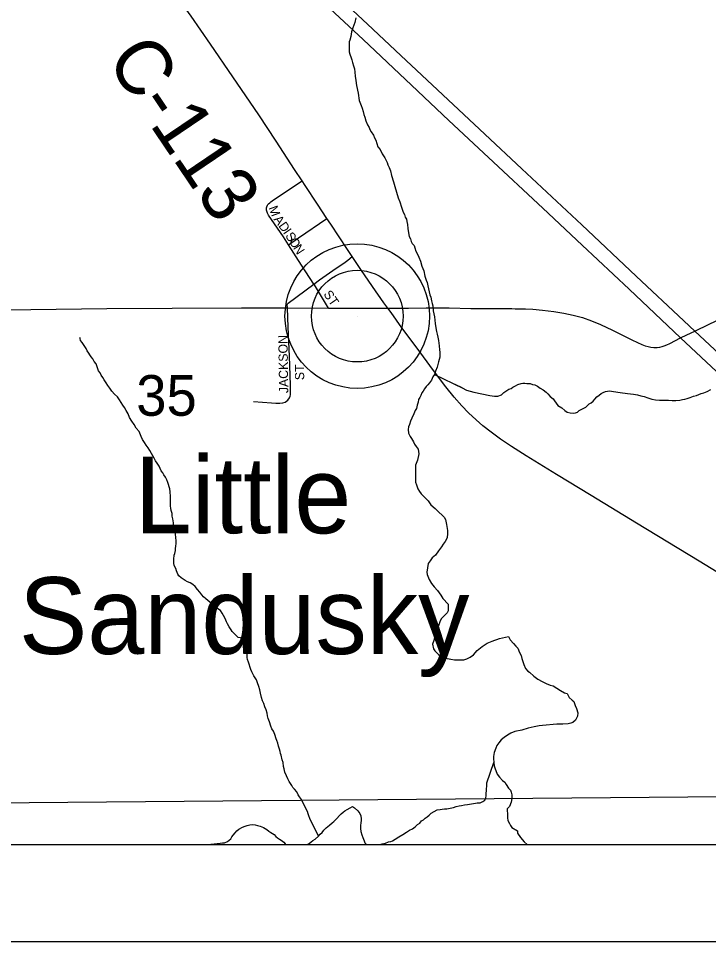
# Model space of a CAD drawing. Extents: x -17 to 88, y -5 to 22.
# Drawn here: x 6.939 to 7.649, y 14 to 14.95 of the extents above; entities that cross this region are included whole.
import ezdxf

# ---------------------------------------------------------------- set-up
doc = ezdxf.new("R2010")
doc.units = 0
for name, color, linetype in [('GM_X_County_Road', 7, 'Continuous'), ('GM_X_County_Road_Text', 7, 'Continuous'), ('GM_X_Minor_River', 7, 'Continuous'), ('GM_X_Section', 7, 'Continuous'), ('GM_X_Section_Text', 7, 'Continuous'), ('GM_X_State_Route', 7, 'Continuous'), ('GM_X_Township', 7, 'Continuous'), ('GM_X_Township_Subdivision', 7, 'Continuous'), ('GM_X_Township_Subdivision_Text', 7, 'Continuous'), ('GM_X_Unincorporated', 7, 'Continuous'), ('GM_X_Unincorporated_Location', 7, 'Continuous'), ('GM_X_Unincorporated_Text', 7, 'Continuous'), ('GM_X_US_Route', 7, 'Continuous'), ('SH_Data', 7, 'Continuous')]:
    doc.layers.add(name, color=color, linetype=linetype)

msp = doc.modelspace()

# ---------------------------------------------------------------- linework, layer by layer
at = {"layer": 'GM_X_County_Road'}
for points in [[(7.2309, 14.78259), (7.22294, 14.79447), (7.20402, 14.82368), (7.18617, 14.8506), (7.17291, 14.87014), (7.15962, 14.88967), (7.13644, 14.92349), (7.11661, 14.95208), (7.09569, 14.98141), (7.08749, 14.99232), (7.07857, 15.00344), (7.06926, 15.01425), (7.05748, 15.02701), (7.04754, 15.03726), (7.03512, 15.04941), (7.0179, 15.06555), (6.98654, 15.09385), (6.97681, 15.10255), (6.96583, 15.1126)], [(7.25648, 14.7439), (7.24662, 14.75874), (7.23401, 14.77795), (7.2309, 14.78259)], [(7.28256, 14.70475), (7.27766, 14.71221), (7.26038, 14.73803), (7.25648, 14.7439)], [(7.31914, 14.65159), (7.31501, 14.65718), (7.30322, 14.67397), (7.2913, 14.69144), (7.28256, 14.70475)], [(7.7683, 14.3128), (7.68455, 14.36403), (7.63944, 14.3915), (7.57509, 14.43041), (7.52832, 14.45879), (7.49286, 14.4806), (7.46153, 14.49967), (7.44626, 14.5093), (7.43495, 14.51702), (7.42537, 14.52397), (7.41704, 14.53053), (7.40994, 14.53663), (7.4022, 14.54388), (7.39527, 14.55107), (7.38752, 14.56003), (7.37898, 14.57075), (7.36625, 14.58763), (7.34919, 14.61056), (7.33354, 14.63148), (7.3224, 14.64718), (7.31914, 14.65159)]]:
    msp.add_lwpolyline(points, dxfattribs=at)
at = {"layer": 'GM_X_Minor_River'}
for points in [[(7.28616, 14.95036), (7.28503, 14.9458), (7.28313, 14.94011), (7.28161, 14.93593), (7.28124, 14.93365), (7.28086, 14.93137), (7.2801, 14.92757), (7.27934, 14.92568), (7.27934, 14.92112), (7.27934, 14.91846), (7.27934, 14.91542), (7.2801, 14.91315), (7.28124, 14.90935), (7.282, 14.90707), (7.28276, 14.90441), (7.2839, 14.90099), (7.28466, 14.89796), (7.28504, 14.89454), (7.28542, 14.89036), (7.28618, 14.88581), (7.28694, 14.88087), (7.28846, 14.8729), (7.2896, 14.8653), (7.2915, 14.86036), (7.29264, 14.85733), (7.29378, 14.85391), (7.29454, 14.85087), (7.2953, 14.84821), (7.29644, 14.84442), (7.29834, 14.84024), (7.29985, 14.83758), (7.30061, 14.83568), (7.30213, 14.83302), (7.30441, 14.82961), (7.30555, 14.82695), (7.30669, 14.82467), (7.30783, 14.82125), (7.30896, 14.81784), (7.31124, 14.8148), (7.31314, 14.81062), (7.31466, 14.80834), (7.31618, 14.80645), (7.31694, 14.80417), (7.31846, 14.80151), (7.31921, 14.79923), (7.32035, 14.79657), (7.32187, 14.79316), (7.32301, 14.78822), (7.32491, 14.78177), (7.32643, 14.77683), (7.32985, 14.76506), (7.33137, 14.76126), (7.33327, 14.75556), (7.33479, 14.75063), (7.3363, 14.74797)], [(7.3363, 14.74797), (7.33707, 14.74531), (7.3382, 14.74341), (7.33858, 14.74076), (7.33934, 14.73772), (7.33972, 14.73354), (7.34048, 14.72936), (7.34124, 14.72557), (7.34238, 14.72291), (7.34314, 14.72025), (7.34428, 14.71835), (7.34618, 14.71607), (7.34694, 14.7138), (7.34808, 14.71038), (7.3496, 14.70734), (7.35111, 14.7043), (7.35263, 14.70013), (7.35415, 14.69481), (7.35605, 14.69025), (7.35719, 14.68456), (7.35871, 14.68038), (7.35947, 14.6781), (7.36023, 14.67469), (7.36099, 14.67165), (7.36175, 14.66861), (7.36251, 14.66557), (7.36327, 14.66291), (7.36403, 14.65912), (7.36479, 14.65646), (7.36555, 14.65418), (7.36593, 14.64886), (7.36707, 14.64279), (7.36783, 14.63595), (7.36859, 14.6314), (7.36935, 14.6276), (7.36973, 14.62494), (7.37049, 14.6219), (7.37125, 14.61849), (7.37163, 14.61583), (7.37201, 14.61279), (7.37239, 14.60899), (7.37277, 14.60634), (7.37277, 14.6014), (7.37125, 14.59646), (7.37049, 14.5938), (7.36974, 14.59114), (7.36822, 14.58697), (7.36708, 14.58355), (7.36557, 14.58089), (7.36405, 14.57747), (7.36215, 14.57482), (7.36026, 14.57292), (7.35874, 14.57102), (7.35684, 14.56874), (7.35533, 14.56646), (7.35419, 14.56456), (7.35305, 14.5619), (7.35191, 14.55963), (7.35077, 14.55773), (7.3504, 14.55507), (7.34926, 14.55203), (7.3485, 14.54861), (7.34736, 14.54633), (7.34585, 14.54292), (7.34395, 14.53836), (7.34243, 14.53532), (7.3413, 14.5319), (7.34054, 14.52963), (7.34016, 14.52697), (7.34054, 14.52317), (7.34206, 14.51975), (7.34357, 14.51747), (7.34547, 14.51406), (7.34661, 14.51178), (7.34813, 14.5095), (7.35041, 14.50646), (7.35117, 14.50191), (7.34965, 14.49545), (7.34814, 14.49203), (7.34776, 14.49013), (7.34776, 14.47608), (7.34776, 14.47267), (7.34852, 14.47001), (7.35004, 14.46583), (7.35156, 14.46317), (7.35346, 14.46052), (7.35611, 14.45786), (7.35839, 14.45596), (7.36067, 14.4533), (7.36332, 14.4495), (7.36788, 14.44571), (7.37167, 14.44191), (7.37509, 14.43888), (7.37699, 14.4366), (7.37851, 14.43432), (7.37965, 14.429), (7.38041, 14.42293), (7.38041, 14.41989), (7.38003, 14.41533), (7.37814, 14.41153), (7.37624, 14.40888)], [(7.10039, 14.40428), (7.10077, 14.40694), (7.10115, 14.4096), (7.10115, 14.41226), (7.10077, 14.41567), (7.10039, 14.41909), (7.10001, 14.42251), (7.09887, 14.42669), (7.09849, 14.43086), (7.09773, 14.43504), (7.09696, 14.4377), (7.09696, 14.44035), (7.09621, 14.44339), (7.09583, 14.44605), (7.09545, 14.44795), (7.09544, 14.45023), (7.09544, 14.45402), (7.09544, 14.45782), (7.09506, 14.46276), (7.09468, 14.4658), (7.09278, 14.47225), (7.09164, 14.47491), (7.09012, 14.47795), (7.08861, 14.48023), (7.08747, 14.48213), (7.08595, 14.4844), (7.08481, 14.48668), (7.08367, 14.48896), (7.08177, 14.49238), (7.07988, 14.49466), (7.07874, 14.49731), (7.07722, 14.49959), (7.0757, 14.50225), (7.07418, 14.50529), (7.07228, 14.50794), (7.07039, 14.5106), (7.06849, 14.51364), (7.06659, 14.51668), (7.06507, 14.51971), (7.06317, 14.52465), (7.06014, 14.52807), (7.05786, 14.53187), (7.05558, 14.53528), (7.0533, 14.53908), (7.05178, 14.54288), (7.04989, 14.54629), (7.04799, 14.54933), (7.04647, 14.55199), (7.04457, 14.55465), (7.04305, 14.55731), (7.04078, 14.56034), (7.03774, 14.56338), (7.03508, 14.56642), (7.03281, 14.56946), (7.03091, 14.57211), (7.02901, 14.57477), (7.02711, 14.57781), (7.02559, 14.58047), (7.02408, 14.58274), (7.02294, 14.58502), (7.02142, 14.5873), (7.02028, 14.59034), (7.01876, 14.59452), (7.01686, 14.59679), (7.01534, 14.59945), (7.01383, 14.60173), (7.01231, 14.60363), (7.01117, 14.60553), (7.00965, 14.60781), (7.00851, 14.61008), (7.00433, 14.61654), (7.00282, 14.61844), (7.00244, 14.62033), (7.00206, 14.62109), (7.00282, 14.62148)], [(7.36708, 14.58355), (7.39554, 14.56988), (7.38833, 14.5733), (7.39554, 14.56988), (7.4001, 14.56723), (7.40769, 14.56533), (7.424, 14.56191), (7.42894, 14.56115), (7.43235, 14.56116), (7.43615, 14.56267), (7.43842, 14.56495), (7.44146, 14.56685), (7.44373, 14.56837), (7.44601, 14.56913), (7.44791, 14.57027), (7.45056, 14.57179), (7.45284, 14.57331), (7.45625, 14.57407), (7.45815, 14.57445), (7.46005, 14.57445), (7.46232, 14.57407), (7.46574, 14.57407), (7.46802, 14.57331), (7.47029, 14.57293), (7.47333, 14.57141), (7.47599, 14.56952), (7.47902, 14.56762), (7.48206, 14.56534), (7.48396, 14.56344), (7.48623, 14.56078), (7.48927, 14.5585), (7.49079, 14.55623), (7.4942, 14.55167), (7.49838, 14.54901), (7.50141, 14.54635), (7.50369, 14.54484), (7.50673, 14.54408), (7.50976, 14.5437), (7.51242, 14.54408), (7.51432, 14.54484), (7.51621, 14.54636), (7.52304, 14.54978), (7.52646, 14.55319), (7.52835, 14.55433), (7.53063, 14.55585), (7.53214, 14.55813), (7.53442, 14.56041), (7.5367, 14.56231), (7.53859, 14.56383), (7.54087, 14.56497), (7.54315, 14.56611), (7.54732, 14.56649), (7.55149, 14.56611), (7.55832, 14.56497), (7.56591, 14.56383), (7.57198, 14.56307), (7.57616, 14.56269), (7.57957, 14.56156), (7.58299, 14.56079), (7.58678, 14.55928), (7.59096, 14.55814), (7.59475, 14.55738), (7.59893, 14.557), (7.6012, 14.557), (7.60462, 14.557), (7.60803, 14.557), (7.61183, 14.55662), (7.61562, 14.55662), (7.61979, 14.557), (7.62245, 14.55776), (7.62473, 14.55814), (7.62738, 14.5589), (7.63042, 14.55966), (7.63383, 14.56118), (7.63687, 14.56194), (7.63914, 14.5627), (7.6418, 14.56384), (7.64446, 14.5646), (7.64787, 14.56612), (7.65167, 14.56802)], [(7.37624, 14.40888), (7.37434, 14.40622), (7.37131, 14.40204), (7.36827, 14.39748), (7.36486, 14.39482), (7.36258, 14.39178), (7.36069, 14.38913), (7.35993, 14.38457), (7.35917, 14.38001), (7.35955, 14.37774), (7.36031, 14.37584), (7.36183, 14.37242), (7.3641, 14.36824), (7.36676, 14.36483), (7.37018, 14.36103), (7.37208, 14.35875), (7.3736, 14.35647), (7.37587, 14.35306), (7.38119, 14.34698), (7.38119, 14.34015), (7.38005, 14.33824), (7.37664, 14.33483), (7.37436, 14.33255), (7.37284, 14.32989), (7.37133, 14.32495), (7.37019, 14.32154), (7.36867, 14.31698), (7.3664, 14.30977), (7.36526, 14.30597), (7.36602, 14.30103), (7.36754, 14.29913), (7.37171, 14.29495), (7.37513, 14.2923), (7.37855, 14.29154), (7.38386, 14.2904), (7.38765, 14.29002), (7.39145, 14.29002), (7.39486, 14.29002), (7.39752, 14.29002), (7.40055, 14.29078), (7.40397, 14.29268), (7.40738, 14.29496), (7.41117, 14.29952), (7.4161, 14.3037), (7.42142, 14.30711), (7.42635, 14.30901), (7.42939, 14.31015), (7.43128, 14.31091), (7.43394, 14.31167), (7.44342, 14.31395), (7.44494, 14.31053), (7.44836, 14.30674), (7.45102, 14.30408), (7.45291, 14.3018), (7.45481, 14.29724), (7.45633, 14.29421), (7.45709, 14.29117), (7.45899, 14.28509), (7.46089, 14.28092), (7.46316, 14.27826), (7.46506, 14.27712), (7.46924, 14.27295), (7.47341, 14.26991), (7.47796, 14.26763), (7.48214, 14.26535), (7.48631, 14.26383), (7.48935, 14.26307), (7.49314, 14.2608), (7.49694, 14.25814), (7.50111, 14.25586), (7.50377, 14.2551), (7.50567, 14.25093), (7.5087, 14.24827), (7.5106, 14.24713), (7.51212, 14.24295), (7.51326, 14.23991), (7.51478, 14.23536), (7.5144, 14.23194), (7.51213, 14.22776), (7.50947, 14.22549), (7.50757, 14.22472), (7.50492, 14.22396), (7.49923, 14.22358), (7.49315, 14.22358), (7.47835, 14.22244), (7.47494, 14.22206), (7.46963, 14.22092), (7.46356, 14.2194), (7.45711, 14.2175), (7.4499, 14.21598), (7.44573, 14.21446), (7.44231, 14.21218), (7.4389, 14.20991), (7.43586, 14.20763), (7.43321, 14.20459), (7.43131, 14.20155), (7.43017, 14.19889), (7.42866, 14.19434), (7.4279, 14.19054), (7.4279, 14.18826), (7.42828, 14.18408)], [(7.24769, 14.10849), (7.23896, 14.12672), (7.23782, 14.12938), (7.23706, 14.13127), (7.2363, 14.13393), (7.23516, 14.13621), (7.23023, 14.14608), (7.22833, 14.14874), (7.22681, 14.15102), (7.22529, 14.15406), (7.22302, 14.15671), (7.22149, 14.15861), (7.22036, 14.16051), (7.2177, 14.16469), (7.21618, 14.16734), (7.21466, 14.17038), (7.21314, 14.17418), (7.21238, 14.1776), (7.21163, 14.18026), (7.21124, 14.18405), (7.21049, 14.18709), (7.20935, 14.19165), (7.20859, 14.19355), (7.20821, 14.19545), (7.20745, 14.1981), (7.20669, 14.20114), (7.20593, 14.20418), (7.20479, 14.20684), (7.20403, 14.20874), (7.20289, 14.21291), (7.20137, 14.21633), (7.19985, 14.21899), (7.19871, 14.22164), (7.19719, 14.2262), (7.19605, 14.22962), (7.1953, 14.23228), (7.19492, 14.23494), (7.19378, 14.23835), (7.19264, 14.24139), (7.1915, 14.24481), (7.18998, 14.24784), (7.18922, 14.25126), (7.18808, 14.25544), (7.18732, 14.25886), (7.18618, 14.26227), (7.18504, 14.26607), (7.1839, 14.26911), (7.18239, 14.27139), (7.18124, 14.27329), (7.18011, 14.27556), (7.17897, 14.27746), (7.17821, 14.27974), (7.17555, 14.28734), (7.17479, 14.29037), (7.17441, 14.29227), (7.17441, 14.29455), (7.17479, 14.29759), (7.17441, 14.30063), (7.17365, 14.30404), (7.17289, 14.30632), (7.17251, 14.30898), (7.17061, 14.31126), (7.16757, 14.3124), (7.16492, 14.31277), (7.16188, 14.31581), (7.15885, 14.31885), (7.15771, 14.32075), (7.15581, 14.32379), (7.15391, 14.32682), (7.15315, 14.3291), (7.15163, 14.33252), (7.15011, 14.33556), (7.1486, 14.33784), (7.1467, 14.34049), (7.14404, 14.34239), (7.14214, 14.34391), (7.13949, 14.34619), (7.1319, 14.35264), (7.12924, 14.35454), (7.12772, 14.35682), (7.12544, 14.35948), (7.12317, 14.36213), (7.12089, 14.36517), (7.11823, 14.36745), (7.11558, 14.36897), (7.11292, 14.37011), (7.11064, 14.37163), (7.10837, 14.37277), (7.10647, 14.37428), (7.10381, 14.37618), (7.10305, 14.37808), (7.10153, 14.3815), (7.10078, 14.38378), (7.09926, 14.38681), (7.09888, 14.38947), (7.09888, 14.39137), (7.09888, 14.39327), (7.09925, 14.39745), (7.10001, 14.39934), (7.10039, 14.40238), (7.10039, 14.40428)], [(7.31123, 14.1), (7.31333, 14.10053), (7.31675, 14.10129), (7.31978, 14.10242), (7.32206, 14.10281), (7.32396, 14.10356), (7.32661, 14.10546), (7.33041, 14.10774), (7.33458, 14.11002), (7.33837, 14.11268), (7.34141, 14.11458), (7.34445, 14.1161), (7.3471, 14.118), (7.34976, 14.12028), (7.35203, 14.1218), (7.35393, 14.12407), (7.35583, 14.12522), (7.35772, 14.12711), (7.35962, 14.12825), (7.36152, 14.13015), (7.36379, 14.13205), (7.36683, 14.13395), (7.36986, 14.13547), (7.3729, 14.13585), (7.37517, 14.13623), (7.37745, 14.13661), (7.37973, 14.13661), (7.38162, 14.13699), (7.38656, 14.13775), (7.38959, 14.13889), (7.39263, 14.13965), (7.3949, 14.14003), (7.39794, 14.14079), (7.40097, 14.14117), (7.40515, 14.14155), (7.40742, 14.14193), (7.40932, 14.14231), (7.41122, 14.14269), (7.41425, 14.14269), (7.41691, 14.14421), (7.41881, 14.14535), (7.41994, 14.14801), (7.42032, 14.14991), (7.42032, 14.15294), (7.4207, 14.15484), (7.4207, 14.15674), (7.42108, 14.16016), (7.42108, 14.1632), (7.42828, 14.18408)], [(7.42828, 14.18408), (7.42866, 14.18067), (7.42942, 14.17877), (7.4317, 14.17231), (7.43398, 14.16927), (7.43701, 14.16586), (7.43967, 14.16396), (7.44081, 14.16168), (7.44347, 14.15788), (7.44536, 14.1556), (7.44612, 14.15371), (7.44688, 14.15105), (7.44688, 14.14725), (7.44613, 14.14345), (7.44423, 14.1389), (7.44196, 14.13662), (7.44234, 14.12978), (7.44234, 14.12713), (7.44272, 14.12447), (7.44423, 14.12143), (7.44537, 14.11953), (7.44689, 14.11725), (7.45259, 14.11384), (7.45259, 14.11156), (7.45562, 14.107), (7.45942, 14.10245), (7.46256, 14.1)], [(7.23612, 14.1), (7.23821, 14.1009), (7.2401, 14.10242), (7.242, 14.10393), (7.24428, 14.10545), (7.24769, 14.10849), (7.24959, 14.11039), (7.25148, 14.11229), (7.25338, 14.11457), (7.25566, 14.11685), (7.25907, 14.11989), (7.26173, 14.12216), (7.26362, 14.12368), (7.26666, 14.12672), (7.26931, 14.12976), (7.27121, 14.13128), (7.2731, 14.13318), (7.275, 14.13432), (7.27728, 14.13584), (7.28032, 14.13774), (7.28259, 14.13888)], [(7.28259, 14.13888), (7.28487, 14.13774), (7.28828, 14.13432), (7.29018, 14.13166), (7.29132, 14.12938), (7.2917, 14.12634), (7.2917, 14.12445), (7.29132, 14.12217), (7.29094, 14.11951), (7.29094, 14.11647), (7.29132, 14.11306), (7.29246, 14.10964), (7.29322, 14.10698), (7.29474, 14.10356), (7.2955, 14.10166), (7.29717, 14.1)], [(7.13691, 14.1), (7.13728, 14.10012), (7.14031, 14.1005), (7.14335, 14.10088), (7.14639, 14.10126), (7.14904, 14.10164), (7.15094, 14.10164), (7.15397, 14.10278), (7.15739, 14.10582), (7.15852, 14.10772), (7.16004, 14.10962), (7.16194, 14.1119), (7.16383, 14.1138), (7.16573, 14.1157), (7.16953, 14.11759), (7.17218, 14.11873), (7.17446, 14.11949), (7.17711, 14.12025), (7.18015, 14.12026), (7.18242, 14.12025), (7.18508, 14.11949), (7.18774, 14.11874), (7.19115, 14.11722), (7.19457, 14.11532), (7.19647, 14.11342), (7.19874, 14.11228), (7.20216, 14.11), (7.20368, 14.10811), (7.20557, 14.10659), (7.20747, 14.10545), (7.20937, 14.10431), (7.21203, 14.10241), (7.21354, 14.10051), (7.21431, 14.1)]]:
    msp.add_lwpolyline(points, dxfattribs=at)
at = {"layer": 'GM_X_Section'}
msp.add_line((6.70958, 14.1), (7.70796, 14.1), dxfattribs=at)
msp.add_lwpolyline([(6.71014, 15.14163), (7.71436, 15.15219), (7.70793, 14.14937), (6.70992, 14.1406)], close=True, dxfattribs=at)
msp.add_lwpolyline([(7.70796, 14.1), (7.70793, 14.14937), (6.70992, 14.1406), (6.70958, 14.1)], dxfattribs=at)
at = {"layer": 'GM_X_State_Route'}
for points in [[(5.95887, 14.64314), (6.03889, 14.64398), (6.2278, 14.64563), (6.29241, 14.64645), (6.36511, 14.64685), (6.56334, 14.64797), (6.71209, 14.64925), (6.74107, 14.6495), (6.81563, 14.64974), (6.95172, 14.65038), (7.03002, 14.65121), (7.09712, 14.65168), (7.16857, 14.65197), (7.21573, 14.652)], [(7.21573, 14.652), (7.25809, 14.65171), (7.31914, 14.65159), (7.33913, 14.65183)], [(7.33913, 14.65183), (7.34054, 14.65184), (7.35855, 14.65189), (7.38216, 14.65192), (7.40451, 14.65147), (7.42501, 14.65143), (7.44674, 14.65121), (7.45009, 14.65117)], [(7.45009, 14.65117), (7.461, 14.65104), (7.46842, 14.65067), (7.47828, 14.64977), (7.48997, 14.64834), (7.50035, 14.64664), (7.51003, 14.6446), (7.51955, 14.64199), (7.52888, 14.63872), (7.53802, 14.63493), (7.55036, 14.62915), (7.57033, 14.61898), (7.57599, 14.61634), (7.58062, 14.61429), (7.58418, 14.61302), (7.58723, 14.61212), (7.58974, 14.61166), (7.59298, 14.6113), (7.59652, 14.61122), (7.59923, 14.61163), (7.60153, 14.6122), (7.6036, 14.61288), (7.60639, 14.61401), (7.60941, 14.61539), (7.62055, 14.62121), (7.62705, 14.62424), (7.63523, 14.62805)], [(7.63523, 14.62805), (7.64979, 14.6354), (7.65646, 14.63845), (7.66073, 14.64026), (7.66616, 14.64215), (7.67101, 14.64371), (7.67577, 14.64511), (7.68079, 14.64643), (7.68465, 14.64725), (7.68885, 14.648), (7.69394, 14.64874), (7.69863, 14.64931), (7.70381, 14.64972), (7.70932, 14.65005), (7.71336, 14.65025), (7.72254, 14.65047), (7.72537, 14.65046)]]:
    msp.add_lwpolyline(points, dxfattribs=at)
at = {"layer": 'GM_X_Township'}
msp.add_line((2.60501, 14.1), (8.70899, 14.1), dxfattribs=at)
at = {"layer": 'GM_X_Township_Subdivision'}
for points in [[(7.19458, 14.75601), (7.19523, 14.75753), (7.19573, 14.75839), (7.19635, 14.75918), (7.19749, 14.76017), (7.19869, 14.76107), (7.2013, 14.76302), (7.2309, 14.78259)], [(7.21697, 14.71687), (7.21188, 14.72523), (7.19922, 14.74284), (7.19617, 14.7475), (7.19511, 14.74954), (7.19444, 14.75135), (7.19417, 14.75252), (7.19408, 14.75367), (7.19425, 14.75486), (7.19458, 14.75601)], [(7.21697, 14.71687), (7.22714, 14.72416), (7.25648, 14.7439)], [(7.24302, 14.6764), (7.23034, 14.69584), (7.21697, 14.71687)], [(7.27227, 14.69696), (7.27387, 14.69808), (7.27781, 14.7011), (7.28256, 14.70475)], [(7.24302, 14.6764), (7.24884, 14.68075), (7.26264, 14.69029), (7.27227, 14.69696)], [(7.21573, 14.652), (7.21556, 14.65504), (7.21597, 14.65609), (7.21667, 14.65674), (7.24302, 14.6764)], [(7.25809, 14.65171), (7.24354, 14.6756), (7.24302, 14.6764)], [(7.21791, 14.55939), (7.21853, 14.56117), (7.21881, 14.56244), (7.21894, 14.5643), (7.21882, 14.57241), (7.21797, 14.60231), (7.21666, 14.63219), (7.21573, 14.652)], [(7.18093, 14.55582), (7.19938, 14.55414), (7.20369, 14.5539), (7.20803, 14.55388), (7.21106, 14.5543), (7.21338, 14.55509), (7.21495, 14.55606), (7.21628, 14.55713), (7.21791, 14.55939)]]:
    msp.add_lwpolyline(points, dxfattribs=at)
at = {"layer": 'GM_X_Unincorporated'}
for radius in [0.0744, 0.04716]:
    msp.add_circle((7.28765, 14.64351), radius, dxfattribs=at)
at = {"layer": 'GM_X_Unincorporated_Location'}
msp.add_line((7.28765, 14.64351), (7.28765, 14.64351), dxfattribs=at)
at = {"layer": 'GM_X_US_Route'}
for points in [[(8.18722, 14.1), (8.15487, 14.12747), (8.10929, 14.16692), (8.06913, 14.20218), (8.04971, 14.21961), (8.01633, 14.25032), (7.97828, 14.28606), (7.91432, 14.34597), (7.87858, 14.37963), (7.8427, 14.41316), (7.79356, 14.45888), (7.7334, 14.51556), (7.67889, 14.56647), (7.62055, 14.62121), (7.56741, 14.67109), (7.51901, 14.71669), (7.47864, 14.75451), (7.42288, 14.8068), (7.38192, 14.8449), (7.34343, 14.88107), (7.29384, 14.92814), (7.22063, 14.99635)], [(7.63523, 14.62805), (7.62381, 14.63872), (7.57485, 14.68464), (7.51869, 14.73741), (7.45696, 14.79517), (7.41889, 14.83089), (7.3326, 14.91152), (7.29824, 14.94395), (7.26242, 14.97751)], [(8.2099, 14.1), (8.17081, 14.13359), (8.11111, 14.18522), (8.07609, 14.21601), (8.05255, 14.23728), (8.00285, 14.28332), (7.94178, 14.34086), (7.88247, 14.39574), (7.82911, 14.44605), (7.77501, 14.49649), (7.70643, 14.56146), (7.63523, 14.62805)]]:
    msp.add_lwpolyline(points, dxfattribs=at)
at = {"layer": 'SH_Data'}
for p, q in [((2.6, 14.1), (9.4, 14.1)), ((2.5, 14), (9.5, 14))]:
    msp.add_line(p, q, dxfattribs=at)

# ---------------------------------------------------------------- texts
at = {"layer": 'GM_X_County_Road_Text'}
msp.add_text('C-113', height=0.056818, rotation=304.06371, dxfattribs=at).set_placement((7.02836, 14.90731))
at = {"layer": 'GM_X_Section_Text'}
msp.add_text('35', height=0.041856, rotation=0.00001, dxfattribs=at).set_placement((7.06015, 14.54098))
at = {"layer": 'GM_X_Township_Subdivision_Text'}
for s, rotation, p in [('M', 289.7886, (7.19625, 14.75507)), ('A', 306.94609, (7.2011, 14.74295)), ('D', 305.12096, (7.20606, 14.73635)), ('I', 304.41737, (7.21084, 14.72956)), ('S', 303.12926, (7.21316, 14.72617)), ('O', 302.64724, (7.21679, 14.72061)), ('N', 302.61704, (7.22129, 14.71359)), ('ST', 304.69079, (7.25245, 14.6661)), ('JACKSON', 90.89601, (7.2167, 14.56429)), ('ST', 90, (7.23299, 14.57759))]:
    msp.add_text(s, height=0.00947, rotation=rotation, dxfattribs=at).set_placement(p)
at = {"layer": 'GM_X_Unincorporated_Text'}
for s, p in [('Little', (7.05848, 14.42005)), ('Sandusky', (6.93932, 14.29588))]:
    msp.add_text(s, height=0.078977, rotation=0.00001, dxfattribs=at).set_placement(p)

doc.saveas('drawing.dxf')
